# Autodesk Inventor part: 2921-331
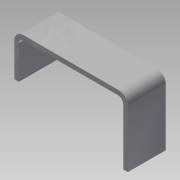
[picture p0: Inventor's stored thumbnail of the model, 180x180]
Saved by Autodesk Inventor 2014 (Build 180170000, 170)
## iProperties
Company: NHTSA/VRTC
Created: 2012-11
Part Number: 2921-331
Material: Steel, Mild
Document SubType Name: Modeling
Designer: Mike Vanvoorhis
Density: 7.86 g/cm^3
Project: CHILD SIDE IMPACT SLED
Description: LIGHT TRAP VANE
Mass: 85.9603 g
Surface Area: 79.1151 cm^2
Volume: 10.9364 cm^3
Appearance: Steel
Stock Number: BAR 25.4 (1") x 3.2 (1/8") x 138.8 (5 7/16")
Author: Dave Walker
Title: Light Trap Vane
Subject: Child Side Impact Sled
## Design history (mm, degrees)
sketch "Sketch1"
  geometry: L1 (0, 0)-(0, 22.225); L2 (6.35, 28.575)-(69.85, 28.575); L3 (76.2, 22.225)-(76.2, -15.875); L4 (76.2, -15.875)-(73.025, -15.875); L5 (0, 0)-(3.175, 0); L6 (3.175, 0)-(3.175, 22.225); L7 (73.025, -15.875)-(73.025, 22.225); L8 (69.85, 25.4)-(6.35, 25.4); A1 r 6.35 centre (69.85, 22.225) between (76.2, 22.225) and (69.85, 28.575); A2 r 3.175 centre (69.85, 22.225) between (73.025, 22.225) and (69.85, 25.4); A3 r 3.175 centre (6.35, 22.225) between (6.35, 25.4) and (3.175, 22.225); A4 r 6.35 centre (6.35, 22.225) between (6.35, 28.575) and (0, 22.225); 2 further points
  constraints: 16 end point, 8 point on circle, 8 tangent, 4 centre point, 4 perpendicular, 3 parallel, 2 point on line, 1 vertical
  dimensions: "d3" = 3.175 distance of L3.end L4.end (= d4); "d4" = 3.175 distance of L1.start L5.end; "d9" = 3.175 radius of A3; "d10" = 6.35 radius of A4; "d11" = 3.175 distance between parallel lines of L2 L8 (= d4); "d12" = 28.575 distance between parallel lines of L2 L5; "d13" = 3.175 radius of A2 (= d9); "d14" = 6.35 radius of A1 (= d10); "d15" = 44.45 distance between parallel lines of L4 L2; "d16" = 76.2 distance between parallel lines of L3 L1
extrude "Extrusion1" new body sketch "Sketch1" distance "d7" = 25.4; taper "d8" = 0 deg
body "Solid1"
